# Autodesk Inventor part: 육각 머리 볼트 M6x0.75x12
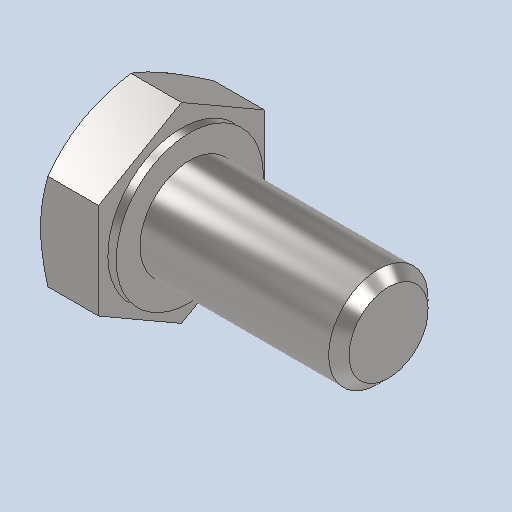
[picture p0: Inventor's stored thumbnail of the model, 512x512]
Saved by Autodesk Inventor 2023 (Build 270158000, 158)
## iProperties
Created: 2024-09
Part Number: 육각 머리 볼트 M6x0.75x12
Material: 강철, 연강
Description: 6각 머리 볼트 및 6각 머리 나사
Document SubType Name: Modeling
Designer: home
Density: 7.85 g/cm^3
Appearance: 기본값
Author: jhkim
Sending System: Autodesk Inventor 2025
Preprocessor: ST-DEVELOPER v20
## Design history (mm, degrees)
feature "Solid1"
node "솔리드1"
